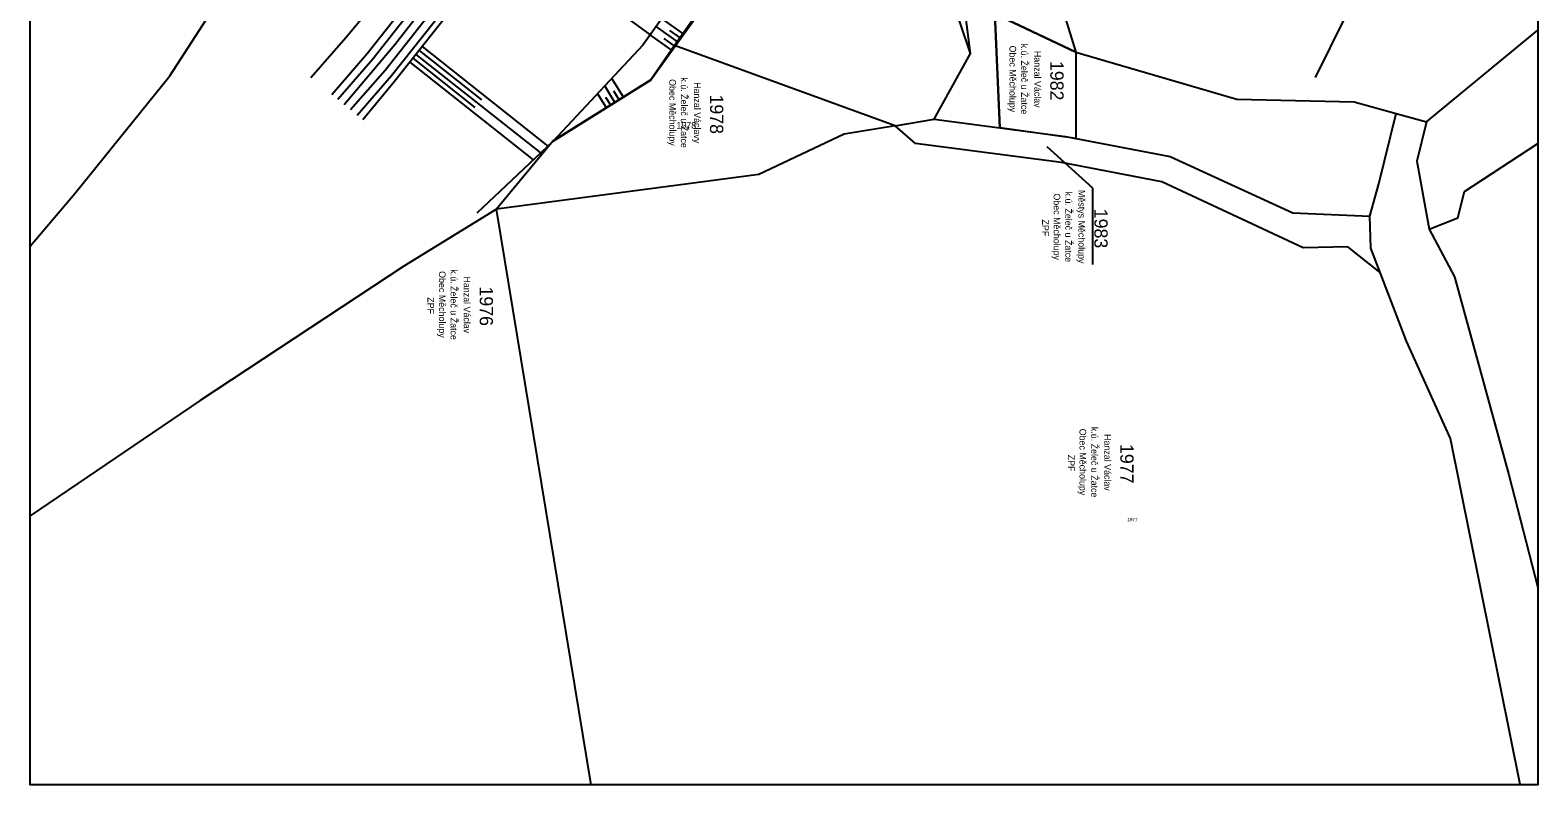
# Model space of a CAD drawing. Extents: x -801372 to -800991, y -1017235 to -1016862.
# Drawn here: x -801218 to -800990.8, y -1017234.8 to -1017121 of the extents above; entities that cross this region are included whole.
import ezdxf

# ---------------------------------------------------------------- set-up
doc = ezdxf.new("R2010")
doc.units = 0
for name, color, linetype in [('05a - kolej - svršek', 7, 'Continuous'), ('09 - stávající terén', 7, 'Continuous'), ('19 - katastr', 7, 'Continuous'), ('19b - katastr - hranice SŽDC', 7, 'Continuous'), ('19b - katastr popisy', 7, 'Continuous'), ('23 - neviditelná', 7, 'Continuous'), ('26 - obvod_stavby', 7, 'Continuous'), ('27 - dočasné zábory', 7, 'Continuous'), ('Vrstva 1 - kolej', 7, 'Continuous'), ('Vrstva 48 - svahy', 7, 'Continuous')]:
    doc.layers.add(name, color=color, linetype=linetype)

msp = doc.modelspace()

# ---------------------------------------------------------------- linework, layer by layer
for points in [[(-801079.49, -1017062.75), (-801060.39, -1017124.37)], [(-801072.61, -1017118.61), (-801071.85, -1017135.76)], [(-801060.39, -1017124.37), (-801060.39, -1017137.35)]]:
    msp.add_lwpolyline(points)
at = {"layer": '05a - kolej - svršek'}
for p, q in [((-801156.79, -1017111.49), (-801167.18, -1017124.59)), ((-801155.83, -1017112.1), (-801166.31, -1017125.44)), ((-801153.73, -1017113.52), (-801164.48, -1017127.15)), ((-801152.66, -1017114.26), (-801163.52, -1017127.93)), ((-801167.18, -1017124.59), (-801172.49, -1017130.78)), ((-801166.31, -1017125.44), (-801171.61, -1017131.5)), ((-801164.48, -1017127.15), (-801169.69, -1017133.07)), ((-801163.52, -1017127.93), (-801168.66, -1017133.91))]:
    msp.add_line(p, q, dxfattribs=at)
at = {"layer": '09 - stávající terén'}
for p, q in [((-801159.87, -1017109.48), (-801170.36, -1017122.16)), ((-801117.79, -1017112.29), (-801125.65, -1017123.33)), ((-801151.89, -1017114.68), (-801163.06, -1017128.79)), ((-801116.81, -1017117.96), (-801124.43, -1017128.57)), ((-801019.85, -1017119.16), (-801024.33, -1017128.18)), ((-801170.36, -1017122.16), (-801175.64, -1017128.22)), ((-801125.65, -1017123.33), (-801139.21, -1017137.8)), ((-801163.06, -1017128.79), (-801167.85, -1017134.57)), ((-801124.43, -1017128.57), (-801139.21, -1017137.8)), ((-801139.21, -1017137.8), (-801150.65, -1017148.6))]:
    msp.add_line(p, q, dxfattribs=at)
at = {"layer": '19 - katastr'}
for p, q in [((-801076.29, -1017124.55), (-801077.69, -1017113.44)), ((-801087.64, -1017135.44), (-801120.85, -1017123.38)), ((-801081.77, -1017134.46), (-801076.29, -1017124.55)), ((-801012.13, -1017133.6), (-801007.59, -1017134.85)), ((-801087.64, -1017135.44), (-801081.77, -1017134.46))]:
    msp.add_line(p, q, dxfattribs=at)
for points in [[(-801076.29, -1017124.55), (-801079.17, -1017115.86), (-801081.08, -1017110), (-801091.59, -1017105.94), (-801107.38, -1017104.16)], [(-801077.69, -1017113.44), (-801072.61, -1017118.61), (-801060.39, -1017124.37), (-801036.16, -1017131.43), (-801018.45, -1017131.86), (-801012.13, -1017133.6)], [(-801007.59, -1017134.85), (-800990.79, -1017121.07)], [(-801016.11, -1017149.08), (-801014.73, -1017144.22), (-801012.13, -1017133.6)], [(-801087.64, -1017135.44), (-801095.3, -1017136.72), (-801108.14, -1017142.81), (-801147.67, -1017148.04)], [(-801014.57, -1017157.55), (-801019.43, -1017153.68), (-801026.14, -1017153.86), (-801047.43, -1017143.9), (-801062.58, -1017141), (-801084.58, -1017138.12), (-801087.64, -1017135.44)], [(-801081.77, -1017134.46), (-801061.94, -1017137.05), (-801046.19, -1017140.07), (-801027.73, -1017148.59), (-801016.11, -1017149.08)], [(-801007.59, -1017134.85), (-801009.05, -1017140.81), (-801007.17, -1017151.05)], [(-801007.17, -1017151.05), (-801002.87, -1017149.33), (-801001.86, -1017145.37), (-800990.79, -1017138.11)], [(-801133.45, -1017234.77), (-801147.67, -1017148.04)], [(-801014.57, -1017157.55), (-801015.97, -1017153.92), (-801016.11, -1017149.08)], [(-801007.17, -1017151.05), (-801003.34, -1017158.2), (-800995.15, -1017188.06), (-800990.79, -1017205.02)], [(-800993.47, -1017234.72), (-801003.97, -1017182.58), (-801010.59, -1017167.92), (-801014.57, -1017157.55)]]:
    msp.add_lwpolyline(points, dxfattribs=at)
at = {"layer": '19b - katastr - hranice SŽDC'}
msp.add_line((-801107.38, -1017104.16), (-801120.85, -1017123.38), dxfattribs=at)
for points in [[(-801217.95, -1017153.62), (-801211.22, -1017145.68), (-801196.91, -1017127.94), (-801187.5, -1017113.35), (-801179.48, -1017100.28)], [(-801120.85, -1017123.38), (-801124.46, -1017128.53), (-801139.16, -1017137.71), (-801147.67, -1017148.04)], [(-801147.67, -1017148.04), (-801161.67, -1017156.6), (-801192.33, -1017176.83), (-801217.95, -1017194.25)]]:
    msp.add_lwpolyline(points, dxfattribs=at)
at = {"layer": '19b - katastr popisy'}
for p, q in [((-801057.83, -1017144.85), (-801064.74, -1017138.64)), ((-801057.83, -1017156.38), (-801057.83, -1017144.85))]:
    msp.add_line(p, q, dxfattribs=at)
at = {"layer": '23 - neviditelná'}
msp.add_lwpolyline([(-801217.95, -1016905.67), (-800990.79, -1016905.67), (-800990.79, -1017234.77), (-801217.95, -1017234.77)], close=True, dxfattribs=at)
at = {"layer": '26 - obvod_stavby'}
msp.add_lwpolyline([(-801085, -1017062.08), (-801079.49, -1017062.75), (-801060.39, -1017124.37), (-801060.39, -1017137.35), (-801071.85, -1017135.76), (-801072.61, -1017118.61), (-801086.97, -1017066.29), (-801086.64, -1017070.52), (-801095.48, -1017082.49), (-801141.22, -1017053.25), (-801148.66, -1017042.44), (-801151.48, -1017039.58)], dxfattribs=at)
at = {"layer": '27 - dočasné zábory'}
for points in [[(-801072.61, -1017118.61), (-801086.97, -1017066.29), (-801085.03, -1017062.08), (-801079.49, -1017062.75), (-801060.39, -1017124.37), (-801072.61, -1017118.61)], [(-801072.61, -1017118.61), (-801060.39, -1017124.37), (-801060.39, -1017137.35), (-801071.85, -1017135.76), (-801072.61, -1017118.61)]]:
    msp.add_lwpolyline(points, dxfattribs=at)
at = {"layer": 'Vrstva 1 - kolej'}
for p, q in [((-801154.45, -1017112.23), (-801163.02, -1017123.28)), ((-801163.02, -1017123.28), (-801170.62, -1017132.31))]:
    msp.add_line(p, q, dxfattribs=at)
at = {"layer": 'Vrstva 48 - svahy'}
for p, q in [((-801145.7, -1017106.24), (-801124.54, -1017121.76)), ((-801120.34, -1017122.88), (-801123.65, -1017120.51)), ((-801119.47, -1017121.66), (-801122.78, -1017119.29)), ((-801121.22, -1017124.1), (-801124.52, -1017121.73)), ((-801120.78, -1017123.49), (-801122.43, -1017122.31)), ((-801119.91, -1017122.27), (-801121.56, -1017121.09)), ((-801160.29, -1017125.29), (-801150.95, -1017132.68)), ((-801159.82, -1017124.7), (-801141.06, -1017139.55)), ((-801159.36, -1017124.11), (-801149.93, -1017131.57)), ((-801158.89, -1017123.52), (-801139.96, -1017138.51)), ((-801160.75, -1017125.87), (-801142.16, -1017140.59)), ((-801129.84, -1017131.95), (-801131.39, -1017129.46)), ((-801128.57, -1017131.15), (-801130.33, -1017128.33)), ((-801131.11, -1017132.74), (-801132.46, -1017130.59)), ((-801130.47, -1017132.35), (-801131.2, -1017131.19)), ((-801129.2, -1017131.55), (-801130.03, -1017130.22))]:
    msp.add_line(p, q, dxfattribs=at)

# ---------------------------------------------------------------- texts
at = {"layer": '19b - katastr popisy'}
for s, height, p in [('Obec Měcholupy', 1.0001, (-801070.4, -1017123.37)), ('k.ú. Želeč u Žatce ', 1.0001, (-801068.65, -1017123.09)), ('Hanzal Václav', 1.0001, (-801066.66, -1017124.17)), ('1982', 2, (-801064.25, -1017125.69)), ('Obec Měcholupy', 1.0001, (-801121.66, -1017128.43)), ('k.ú. Želeč u Žatce ', 1.0001, (-801119.91, -1017128.16)), ('Hanzal Václavy', 1.0001, (-801117.93, -1017128.88)), ('1978', 2, (-801115.52, -1017130.74)), ('Obec Měcholupy', 1.0001, (-801063.75, -1017145.65)), ('k.ú. Želeč u Žatce ', 1.0001, (-801062, -1017145.38)), ('Městys Měcholupy', 1.0001, (-801060.01, -1017145.13)), ('ZPF', 1, (-801065.48, -1017149.58)), ('1983', 2, (-801057.61, -1017147.96)), ('Obec Měcholupy', 1.0001, (-801156.36, -1017157.36)), ('k.ú. Želeč u Žatce ', 1.0001, (-801154.61, -1017157.09)), ('Hanzal Václav', 1.0001, (-801152.62, -1017158.16)), ('ZPF', 1, (-801158.09, -1017161.29)), ('1976', 2, (-801150.22, -1017159.67)), ('Obec Měcholupy', 1.0001, (-801059.85, -1017181.1)), ('k.ú. Želeč u Žatce ', 1.0001, (-801058.09, -1017180.83)), ('Hanzal Václav', 1.0001, (-801056.11, -1017181.91)), ('1977', 2, (-801053.7, -1017183.41)), ('ZPF', 1, (-801061.58, -1017185.03))]:
    msp.add_text(s, height=height, rotation=270, dxfattribs=at).set_placement(p)
for s, height, p in [('1978', 1, (-801120.58, -1017135.89)), ('1977', 0.5, (-801052.64, -1017195.04))]:
    msp.add_text(s, height=height, dxfattribs=at).set_placement(p)

doc.saveas('drawing.dxf')
